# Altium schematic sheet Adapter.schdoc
size 243 x 91 mm
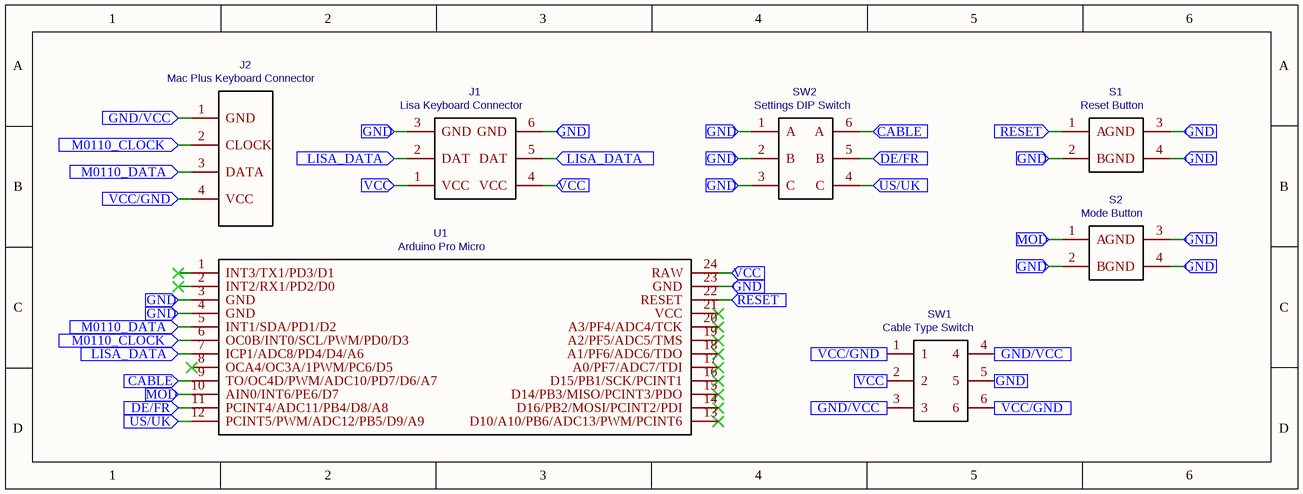
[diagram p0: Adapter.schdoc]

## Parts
J1  Lisa Keyboard Connector  [TRS_STEREO_0.25_INCH]
J2  Mac Plus Keyboard Connector  [MAC_KBD_CONNECTOR_ALT]
S1  Reset Button  [TACT_SWITCH_RIGHT_ANGLE_6MM]
S2  Mode Button  [TACT_SWITCH_RIGHT_ANGLE_6MM]
SW1  Cable Type Switch  [DPDT_SLIDER_SWITCH]
SW2  Settings DIP Switch  [DIP_SWITCH_3POS]
U1  Arduino Pro Micro  [ARDUINO_PRO_MICRO]

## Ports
CABLE (in), DE/FR (in), GND (in), GND/VCC (in), LISA_DATA (in), M0110_CLOCK (in), M0110_DATA (in), MOD (in), RESET (in), US/UK (in), VCC (in), VCC/GND (in)

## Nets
CABLE: SW2.6(A) U1.9(TO/OC4D/PWM/ADC10/PD7/D6/A7) ; port CABLE
DE/FR: SW2.5(B) U1.11(PCINT4/ADC11/PB4/D8/A8) ; port DE/FR
GND: J1.3(GND) J1.6(GND) S1.2(B) S1.3(GND) S1.4(GND) S2.2(B) S2.3(GND) S2.4(GND) SW1.5 SW2.1(A) SW2.2(B) SW2.3(C) U1.3(GND) U1.4(GND) U1.23(GND) ; port GND
GND/VCC: J2.1(GND) SW1.3 SW1.4 ; port GND/VCC
LISA_DATA: J1.2(DAT) J1.5(DAT) U1.7(ICP1/ADC8/PD4/D4/A6) ; port LISA_DATA
M0110_CLOCK: J2.2(CLOCK) U1.6(OC0B/INT0/SCL/PWM/PD0/D3) ; port M0110_CLOCK
M0110_DATA: J2.3(DATA) U1.5(INT1/SDA/PD1/D2) ; port M0110_DATA
MOD: S2.1(A) U1.10(AIN0/INT6/PE6/D7) ; port MOD
RESET: S1.1(A) U1.22(RESET) ; port RESET
US/UK: SW2.4(C) U1.12(PCINT5/PWM/ADC12/PB5/D9/A9) ; port US/UK
VCC: J1.1(VCC) J1.4(VCC) SW1.2 U1.24(RAW) ; port VCC
VCC/GND: J2.4(VCC) SW1.1 SW1.6 ; port VCC/GND

Not connected (* = marked no-connect by the designer): U1 1(INT3/TX1/PD3/D1)* 2(INT2/RX1/PD2/D0)* 8(OCA4/OC3A/1PWM/PC6/D5)* 13(D10/A10/PB6/ADC13/PWM/PCINT6)* 14(D16/PB2/MOSI/PCINT2/PDI)* 15(D14/PB3/MISO/PCINT3/PDO)* 16(D15/PB1/SCK/PCINT1)* 17(A0/PF7/ADC7/TDI)* 18(A1/PF6/ADC6/TDO)* 19(A2/PF5/ADC5/TMS)* 20(A3/PF4/ADC4/TCK)* 21(VCC)*

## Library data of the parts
J1 = Lisa Keyboard Connector: Contributor: William Tooker
J2 = Mac Plus Keyboard Connector: Contributor: William Tooker
S1 = Reset Button: Contributor: William Tooker
S2 = Mode Button: Contributor: William Tooker
SW1 = Cable Type Switch: BOM_Manufacturer: C&K; Contributor: William Tooker
SW2 = Settings DIP Switch: BOM_Manufacturer: Wurth Elektronik; BOM_Manufacturer Part: 418117270903; Contributor: will_tooker
U1 = Arduino Pro Micro: Contributor: will_tooker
